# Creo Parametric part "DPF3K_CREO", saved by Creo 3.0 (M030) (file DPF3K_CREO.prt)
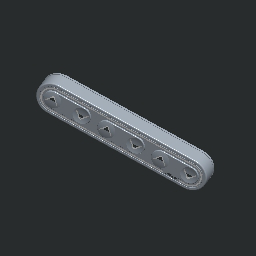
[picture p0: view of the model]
Units: millimeter Newton Second (mmNs); MM, TONNE, SECS

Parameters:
  PTC_COMMON_NAME = "dpf3k_creo.prt"
  PTC_WM_ITERATION = "18"
  PTC_WM_VERSION = "-.18"
  PTC_WM_LIFECYCLE_STATE = "Released"
  PTC_WM_LIFECYCLE = "Linak CAD"
  PTC_WM_LOCATION = "/Libraries/Templates/Start"
  PTC_WM_CREATED_BY = "orgadmin"
  PTC_WM_CREATED_ON = "2006-03-03"
  PTC_WM_MODIFIED_BY = "orgadmin"
  PTC_WM_MODIFIED_ON = "2014-08-14"
  PTC_WM_TEAM = "Default"
  PDMREV = "-.18"
  PDMRL = "Released"
  PROI_VERSION = "18"
  PROI_RELEASE = "Released"
  INITIATEDBY = "orgadmin"
  PTC_WM_CREATED_BY_ORIG = "orgadmin"

Created from: START_PART.PRT

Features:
  1. datum plane "RIGHT"
  2. datum plane "TOP"
  3. datum plane "FRONT"
  4. coordinate system
  5. datum axis
  6. datum axis
  7. datum axis
  8. imported feature "Import Feature id 47"
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
Other named items: X-AXES, Y-AXES, Z-AXES, CS0

Layers: ANNOTATIONS, AXES, COSMETICS, CSYS, CURVES, EXT_COPY_GEOM, PLANES, POINTS, PUBLISHED_GEOM, QUILTS, SOLIDS, STARTUP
